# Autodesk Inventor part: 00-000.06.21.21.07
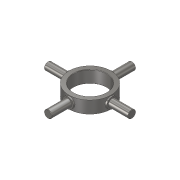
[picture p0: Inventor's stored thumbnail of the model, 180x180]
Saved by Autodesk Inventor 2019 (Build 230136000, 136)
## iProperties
Created: 2019-01
Part Number: 00-000.06.21.21.07
Material: Steel, Mild
Document SubType Name: Modeling
Designer: m.vorobev
Density: 7.85 g/cm^3
Appearance: Semi-Polished
Author: m.vorobev
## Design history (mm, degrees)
sketch "Sketch1"
  geometry: L1 (43, 16)-(55, 16); L2 (55, 16)-(55, -16); L3 (55, -16)-(43, -16); L4 (43, -16)-(43, 16); L5 (0, 0)-(19.028, 0); L6 (19.028, 0)-(19.028, 10.694); L7 (19.028, 10.694)-(0, 10.694); L8 (0, 10.694)-(0, 0); 1 further point
  constraints: 16 end point, 4 parallel, 2 horizontal, 2 perpendicular, 1 horizontal alignment, 1 midpoint
  dimensions: "d0" = 110 diameter of L2 L8; "d1" = 86 diameter of L4 L8; "d2" = 32 distance of L1.end L2.end
revolve "Revolution1" sketch "Sketch1" stored, may be unused: angle "d3" = 90 deg
chamfer "Chamfer1" distance "d4" = 1; stored, may be unused: second distance "d5" = 2, angle "d6" = 45 deg
sketch "Sketch2"
  geometry: L1 (0, -48.987)-(-10, -48.987); L2 (-10, -48.987)-(-10, -110); L3 (-10, -110)-(0, -110); L4 (0, -110)-(0, -48.987); L5 (0, -58)-(-14, -58); L6 (-14, -58)-(-14, -47.209); L7 (-14, -47.209)-(0, -47.209); L8 (0, -47.209)-(0, -58); L9 (0, 0)-(-16.492, 0); 1 further point
  constraints: 18 end point, 4 parallel, 3 horizontal, 2 perpendicular, 1 midpoint, 1 point on line, 1 vertical alignment
  dimensions: "d7" = 20 diameter of L2 L4; "d8" = 28 diameter of L6 L4; "d9" = 116 diameter of L5 L9; "d10" = 220 diameter of L3 L9
revolve "Revolution2" sketch "Sketch2" stored, may be unused: angle "d11" = 90 deg
chamfer "Chamfer2" distance "d12" = 1; stored, may be unused: second distance "d13" = 2, angle "d14" = 45 deg
pattern_circular "Circular Pattern1" dims angle "d16" = 360 deg
body "Solid1"
